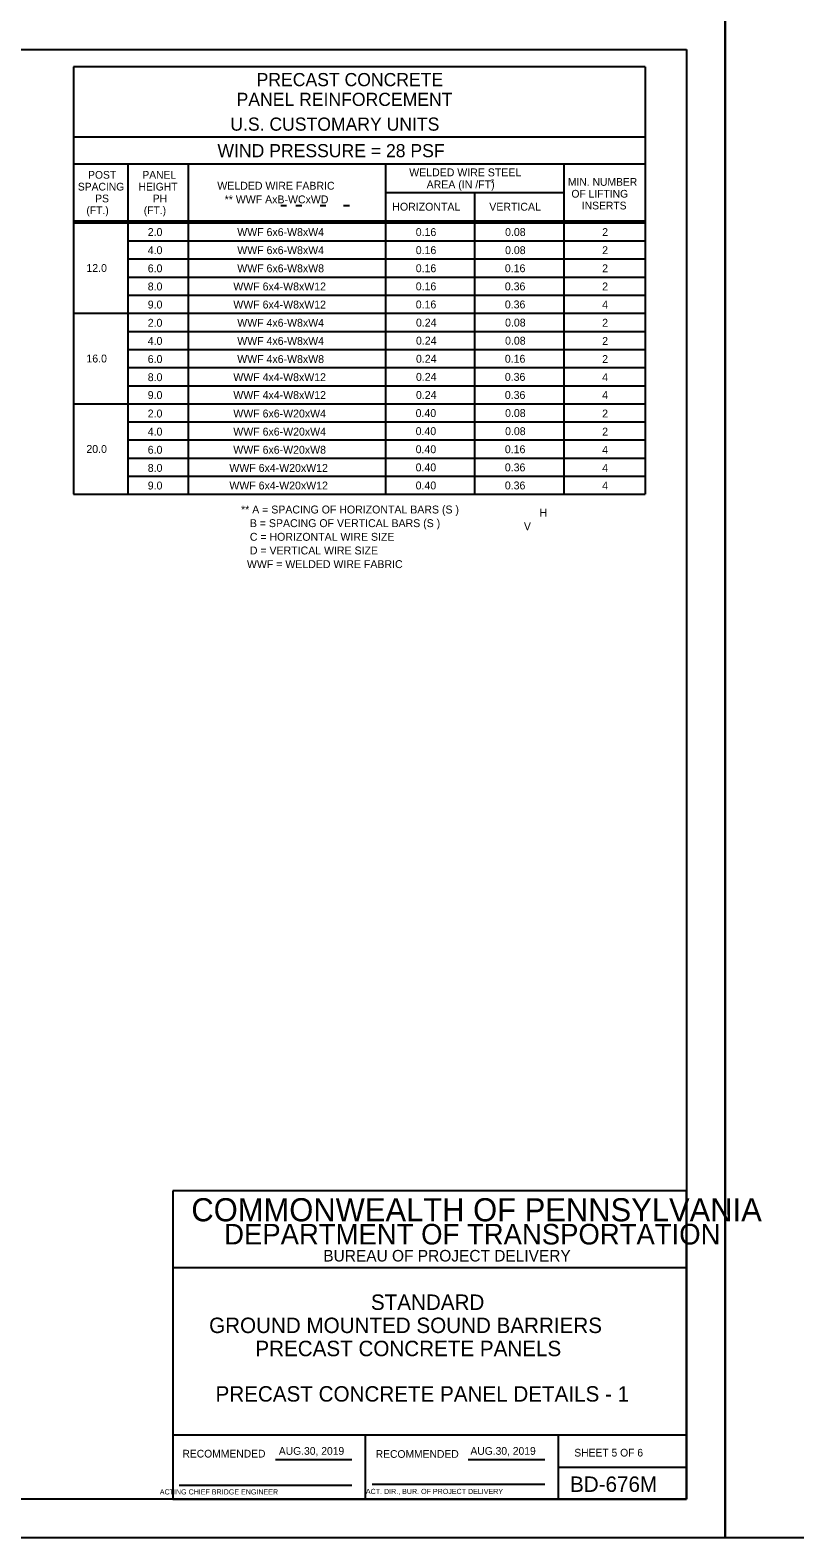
# Model space of a CAD drawing. Extents: x 3761 to 5458, y -616 to 1166.
# Drawn here: x 4332 to 4629, y -616 to -30 of the extents above; entities that cross this region are included whole.
import ezdxf

# ---------------------------------------------------------------- set-up
doc = ezdxf.new("R2010")
doc.units = 0
for name, color, linetype in [('1', 7, 'Continuous'), ('2', 7, 'Continuous'), ('PLT-BNDY', 7, 'Continuous')]:
    doc.layers.add(name, color=color, linetype=linetype)

msp = doc.modelspace()

# ---------------------------------------------------------------- linework, layer by layer
at = {"layer": '1'}
for p, q in [((4348.69, -44.04), (4348.69, -210.36)), ((4571.19, -44.04), (4348.69, -44.04)), ((4571.19, -44.04), (4571.19, -210.36)), ((4571.19, -71.39), (4348.69, -71.39)), ((4571.19, -81.98), (4348.69, -81.98)), ((4370.02, -210.36), (4370.02, -81.98)), ((4393.35, -81.98), (4393.35, -210.36)), ((4470.15, -81.98), (4470.15, -210.36)), ((4539.49, -81.98), (4539.49, -210.36)), ((4470.15, -92.99), (4539.49, -92.99)), ((4504.82, -92.99), (4504.82, -210.36)), ((4429.35, -98.03), (4431.59, -98.03)), ((4435.31, -98.03), (4437.55, -98.03)), ((4444.73, -98.03), (4446.96, -98.03)), ((4453.86, -98.03), (4456.1, -98.03)), ((4348.69, -104), (4571.19, -104)), ((4348.69, -104.75), (4571.19, -104.75)), ((4370.02, -111.79), (4571.19, -111.79)), ((4370.02, -118.83), (4571.19, -118.83)), ((4370.02, -125.87), (4571.19, -125.87)), ((4370.02, -132.91), (4571.19, -132.91)), ((4348.69, -139.95), (4571.19, -139.95)), ((4370.02, -146.99), (4571.19, -146.99)), ((4370.02, -154.03), (4571.19, -154.03)), ((4370.02, -161.07), (4571.19, -161.07)), ((4370.02, -168.11), (4571.19, -168.11)), ((4348.69, -175.15), (4571.19, -175.15)), ((4370.02, -182.19), (4571.19, -182.19)), ((4370.02, -189.23), (4571.19, -189.23)), ((4370.02, -196.27), (4571.19, -196.27)), ((4370.02, -203.32), (4571.19, -203.32)), ((4348.69, -210.36), (4571.19, -210.36))]:
    msp.add_line(p, q, dxfattribs=at)
at = {"layer": '2'}
for p, q in [((3801.34, -37.31), (4587.34, -37.31)), ((4587.34, -37.31), (4587.34, -601.31)), ((4587.34, -481.31), (4387.34, -481.31)), ((4387.34, -481.31), (4387.34, -601.31)), ((4587.34, -601.31), (4587.34, -481.31)), ((4587.34, -511.31), (4387.34, -511.31)), ((4587.34, -576.31), (4387.34, -576.31)), ((4462.34, -601.31), (4462.34, -576.31)), ((4537.34, -576.31), (4537.34, -601.31)), ((4427.31, -585.81), (4457.07, -585.81)), ((4502.31, -585.81), (4532.21, -585.81)), ((4537.34, -588.81), (4587.34, -588.81)), ((4389.84, -595.81), (4457.07, -595.81)), ((4464.97, -595.43), (4532.21, -595.43)), ((4587.34, -601.31), (3801.34, -601.31)), ((4387.34, -601.31), (4587.34, -601.31))]:
    msp.add_line(p, q, dxfattribs=at)
at = {"layer": 'PLT-BNDY'}
for points in [[(3761.34, -22.31), (4602.34, -22.31), (4602.34, -616.31), (3761.34, -616.31)], [(4602.34, -22.31), (5443.34, -22.31), (5443.34, -616.31), (4602.34, -616.31)]]:
    msp.add_lwpolyline(points, close=True, dxfattribs=at)

# ---------------------------------------------------------------- texts
at = {"layer": '1'}
for s, height, p in [('PRECAST CONCRETE', 5.1168, (4419.99, -51.6)), ('PANEL REINFORCEMENT', 5.1168, (4412.19, -59.28)), ('U.S. CUSTOMARY UNITS', 5.1168, (4409.76, -68.92)), ('WIND PRESSURE = 28 PSF', 5.1168, (4404.74, -79.24)), ('POST', 3, (4354.41, -87.59)), ('PANEL', 3, (4375.52, -87.59)), ('WELDED WIRE STEEL', 3.072, (4479.37, -86.68)), ('2', 1.54, (4511.17, -89.3)), ('MIN. NUMBER', 3, (4541.15, -90.35)), ('SPACING', 3, (4350.41, -92.19)), ('PS', 3, (4357.17, -96.79)), ('HEIGHT', 3, (4374.04, -92.19)), ('PH', 3, (4379.57, -96.79)), ('WELDED WIRE FABRIC', 3.072, (4404.69, -91.87)), ('AREA (IN /FT)', 3.072, (4486.15, -91.36)), ('OF LIFTING', 3, (4542.5, -94.95)), ('(FT.)', 3, (4353.74, -101.39)), ('(FT.)', 3, (4376.07, -101.39)), ('** WWF AxB-WCxWD', 3.072, (4407.55, -97.18)), ('HORIZONTAL', 3.072, (4472.79, -100.03)), ('VERTICAL', 3.072, (4510.53, -100.03)), ('INSERTS', 3, (4546.56, -99.55)), ('2.0', 3.072, (4377.61, -109.89)), ('WWF 6x6-W8xW4', 3.072, (4412.45, -109.89)), ('0.16', 3.072, (4481.92, -109.89)), ('0.08', 3.072, (4516.68, -109.89)), ('2', 3.07, (4554.47, -109.89)), ('4.0', 3.072, (4377.61, -116.94)), ('WWF 6x6-W8xW4', 3.072, (4412.45, -116.94)), ('0.16', 3.072, (4481.92, -116.93)), ('0.08', 3.072, (4516.68, -116.93)), ('2', 3.07, (4554.47, -116.94)), ('12.0', 3.072, (4353.74, -123.88)), ('6.0', 3.072, (4377.62, -124)), ('WWF 6x6-W8xW8', 3.072, (4412.45, -124)), ('0.16', 3.072, (4481.92, -123.97)), ('0.16', 3.072, (4516.59, -123.97)), ('2', 3.07, (4554.47, -124)), ('8.0', 3.072, (4377.62, -131.05)), ('WWF 6x4-W8xW12', 3.072, (4410.92, -131.05)), ('0.16', 3.072, (4481.92, -131.01)), ('0.36', 3.072, (4516.59, -131.01)), ('2', 3.07, (4554.47, -131.05)), ('9.0', 3.072, (4377.62, -138.09)), ('WWF 6x4-W8xW12', 3.072, (4410.92, -138.09)), ('0.16', 3.072, (4481.92, -138.05)), ('0.36', 3.072, (4516.59, -138.05)), ('4', 3.07, (4554.47, -138.09)), ('2.0', 3.072, (4377.61, -145.18)), ('WWF 4x6-W8xW4', 3.072, (4412.45, -145.18)), ('0.24', 3.072, (4482.01, -145.1)), ('0.08', 3.072, (4516.68, -145.1)), ('2', 3.07, (4554.47, -145.18)), ('4.0', 3.072, (4377.61, -152.24)), ('WWF 4x6-W8xW4', 3.072, (4412.45, -152.24)), ('0.24', 3.072, (4482.01, -152.14)), ('0.08', 3.072, (4516.68, -152.14)), ('2', 3.07, (4554.47, -152.24)), ('16.0', 3.072, (4353.74, -159.09)), ('6.0', 3.072, (4377.62, -159.29)), ('WWF 4x6-W8xW8', 3.072, (4412.45, -159.29)), ('0.24', 3.072, (4482.01, -159.18)), ('0.16', 3.072, (4516.59, -159.18)), ('2', 3.07, (4554.47, -159.29)), ('8.0', 3.072, (4377.62, -166.34)), ('WWF 4x4-W8xW12', 3.072, (4410.92, -166.34)), ('0.24', 3.072, (4482.01, -166.22)), ('0.36', 3.072, (4516.59, -166.22)), ('4', 3.07, (4554.47, -166.34)), ('9.0', 3.072, (4377.62, -173.29)), ('WWF 4x4-W8xW12', 3.072, (4410.92, -173.29)), ('0.24', 3.072, (4482.01, -173.26)), ('0.36', 3.072, (4516.59, -173.26)), ('4', 3.07, (4554.47, -173.29)), ('2.0', 3.072, (4377.61, -180.48)), ('WWF 6x6-W20xW4', 3.072, (4410.92, -180.48)), ('0.40', 3.072, (4481.88, -180.3)), ('0.08', 3.072, (4516.68, -180.3)), ('2', 3.07, (4554.47, -180.48)), ('4.0', 3.072, (4377.61, -187.53)), ('WWF 6x6-W20xW4', 3.072, (4410.92, -187.53)), ('0.40', 3.072, (4481.88, -187.34)), ('0.08', 3.072, (4516.68, -187.34)), ('2', 3.07, (4554.47, -187.53)), ('20.0', 3.072, (4353.74, -194.29)), ('6.0', 3.072, (4377.62, -194.58)), ('WWF 6x6-W20xW8', 3.072, (4410.92, -194.58)), ('0.40', 3.072, (4481.88, -194.38)), ('0.16', 3.072, (4516.59, -194.38)), ('4', 3.07, (4554.47, -194.58)), ('8.0', 3.072, (4377.62, -201.63)), ('WWF 6x4-W20xW12', 3.072, (4409.38, -201.63)), ('0.40', 3.072, (4481.88, -201.42)), ('0.36', 3.072, (4516.59, -201.42)), ('4', 3.07, (4554.47, -201.63)), ('9.0', 3.072, (4377.62, -208.49)), ('WWF 6x4-W20xW12', 3.072, (4409.38, -208.49)), ('0.40', 3.072, (4481.88, -208.46)), ('0.36', 3.072, (4516.59, -208.46)), ('4', 3.07, (4554.47, -208.49)), ('   ** A = SPACING OF HORIZONTAL BARS (S )', 3.072, (4410.51, -217.82)), ('H', 3.07, (4530.12, -219.06)), ('      B = SPACING OF VERTICAL BARS (S )', 3.072, (4410.51, -223.13)), ('V', 3.07, (4524.01, -224.32)), ('      C = HORIZONTAL WIRE SIZE', 3.072, (4410.51, -228.44)), ('      D = VERTICAL WIRE SIZE', 3.072, (4410.51, -233.75)), ('     WWF = WELDED WIRE FABRIC', 3.072, (4410.51, -239.06)), ('STANDARD', 6, (4464.48, -527.64)), ('GROUND MOUNTED SOUND BARRIERS', 6, (4401.5, -536.64)), ('PRECAST CONCRETE PANELS', 6, (4419.5, -545.64)), ('PRECAST CONCRETE PANEL DETAILS - 1', 6, (4404, -563.31)), ('SHEET 5 OF 6', 3, (4543.63, -584.68)), ('BD-676M', 6, (4541.97, -598.43))]:
    msp.add_text(s, height=height, dxfattribs=at).set_placement(p)
at = {"layer": '2'}
for s, height, p in [('COMMONWEALTH OF PENNSYLVANIA', 9, (4394.59, -493.18)), ('DEPARTMENT OF TRANSPORTATION', 8.0002, (4407.34, -502.18)), ('BUREAU OF PROJECT DELIVERY', 4.5, (4445.93, -508.81)), ('AUG.30, 2019', 3, (4428.64, -584)), ('AUG.30, 2019', 3, (4503.19, -584)), ('       ACTING CHIEF BRIDGE ENGINEER', 2.0002, (4376.93, -599.43)), ('  ACT. DIR., BUR. OF PROJECT DELIVERY', 2.0002, (4460.97, -599.25))]:
    msp.add_text(s, height=height, dxfattribs=at).set_placement(p)
for p in [(4391.11, -585.06), (4466.33, -585.18)]:
    msp.add_text('RECOMMENDED', height=3, rotation=360, dxfattribs=at).set_placement(p)

doc.saveas('drawing.dxf')
